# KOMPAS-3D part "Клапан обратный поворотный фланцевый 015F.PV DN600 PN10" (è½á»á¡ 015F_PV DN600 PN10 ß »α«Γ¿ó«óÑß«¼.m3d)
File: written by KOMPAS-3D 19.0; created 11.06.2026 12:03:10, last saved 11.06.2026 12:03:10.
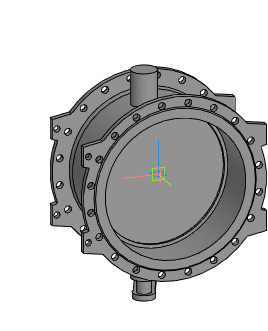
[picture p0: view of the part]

Document properties: Автор: Энергия; Полное имя файла: Z:\3.Личные\kachalov\001_3d для проектировщиков\5.5 Тип 015F.PV Клапан обратный поворотный с двумя эксцентриками\_stp_Клапан 015F.PV DN300-DN1200 с противовесом\Клапан 015F_PV DN600 PN10 с противовесом.m3d

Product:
- Part/product: Клапан обратный поворотный фланцевый 015F.PV DN600 PN10

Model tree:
1. Операция без истории:1
2. Сплайн:1
     Координата Y = 30; Координата Z = 300; Вес = 1; Координата X = 600; Координата Y = 108.991; Координата Z = 300; Вес = 0.333333; Координата X = 600; Координата Y = 108.991; Координата Z = -300; Вес = 0.333333; Координата Y = 30; Координата Z = -300; Вес = 1; Координата X = -600; Координата Y = -48.9915; Координата Z = -300; Вес = 0.333333; Координата X = -600; Координата Y = -48.9915; Координата Z = 300; Вес = 0.333333; Порядок = 4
